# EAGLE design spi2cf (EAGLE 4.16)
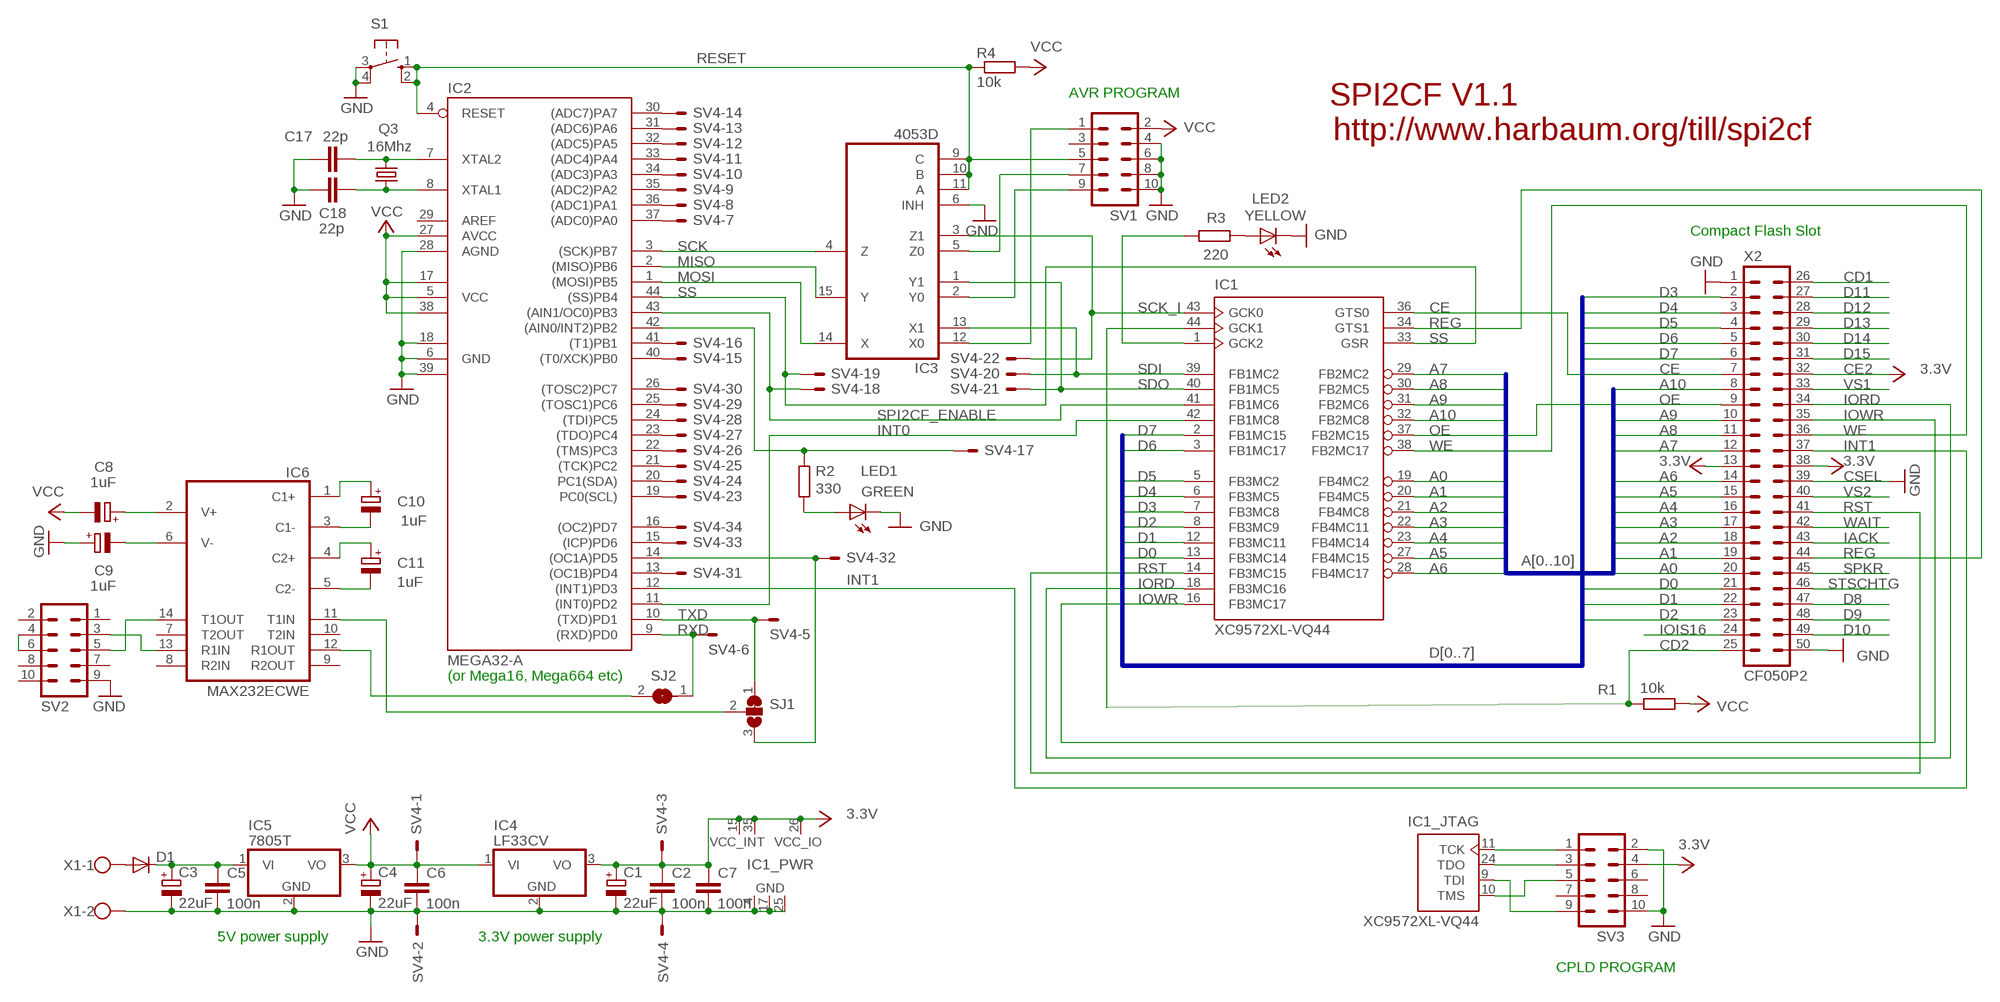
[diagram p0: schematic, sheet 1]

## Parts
C1  22uF  CPOL-EUCT6032  [CT6032]
C2  100n  C-EUC0805  [C0805]
C3  22uF  CPOL-EUCT6032  [CT6032]
C4  22uF  CPOL-EUCT6032  [CT6032]
C5  100n  C-EUC0805  [C0805]
C6  100n  C-EUC0805  [C0805]
C7  100n  C-EUC0805  [C0805]
C8  1uF  CPOL-EUCT3216  [CT3216]
C9  1uF  CPOL-EUCT3216  [CT3216]
C10  1uF  CPOL-EUCT3216  [CT3216]
C11  1uF  CPOL-EUCT3216  [CT3216]
C17  22p  C-EUC0805  [C0805]
C18  22p  C-EUC0805  [C0805]
D1  DIODE-SMC  [SMC]
IC1  XC9572XL-VQ44  [VQ44]
IC2  MEGA32-A  [TQFP44]
IC3  4053D  [SO16]
IC4  LF33CV  7805T  [TO220H]
IC5  7805T  [TO220H]
IC6  MAX232ECWE  [SO16L]
LED1  GREEN  LEDCHIPLED_0805  [CHIPLED_0805]
LED2  YELLOW  LEDCHIPLED_0805  [CHIPLED_0805]
Q3  16Mhz  CRYTALHC49S  [HC49/S]
R1  10k  R-EU_R0805  [R0805]
R2  330  R-EU_R0805  [R0805]
R3  220  R-EU_R0805  [R0805]
R4  10k  R-EU_R0805  [R0805]
S1  10-XX  [B3F-10XX]
SJ1  SJ2W  [SJ_2]
SJ2  SJ  [SJ]
SV1  ML10  [ML10]
SV2  ML10  [ML10]
SV3  ML10  [ML10]
SV4  ML34E  [ML34]
X1  W237-02P  [W237-132]
X2  CF050P2  [CF050P2]

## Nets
A0: IC1.19(FB4MC2) X2.20
A1: IC1.20(FB4MC5) X2.19
A2: IC1.21(FB4MC8) X2.18
A3: IC1.22(FB4MC11) X2.17
A4: IC1.23(FB4MC14) X2.16
A5: IC1.27(FB4MC15) X2.15
A6: IC1.28(FB4MC17) X2.14
A7: IC1.29(FB2MC2) X2.12
A8: IC1.30(FB2MC5) X2.11
A9: IC1.31(FB2MC6) X2.10
A10: IC1.32(FB2MC8) X2.8
CE: IC1.36(GTS0) X2.7
D0: IC1.13(FB3MC14) X2.21
D1: IC1.12(FB3MC11) X2.22
D2: IC1.8(FB3MC9) X2.23
D3: IC1.7(FB3MC8) X2.2
D4: IC1.6(FB3MC5) X2.3
D5: IC1.5(FB3MC2) X2.4
D6: IC1.3(FB1MC17) X2.5
D7: IC1.2(FB1MC15) X2.6
D8: X2.47
D9: X2.48
D10: X2.49
GND [power]: C1.- C2.2 C3.- C4.- C5.2 C6.2 C7.2 C9.+ C17.1 C18.1 IC1.4(GND) IC1.17(GND) IC1.25(GND) IC2.6(GND) IC2.18(GND1) IC2.28(AGND) IC2.39(GND2) IC3.6(INH) IC4.2(GND) IC5.2(GND) LED1.C LED2.C S1.3(P) S1.4(P1) SV1.4 SV1.6 SV1.8 SV1.10 SV2.9 SV3.2 SV3.10 SV4.2 SV4.4 X1.2 X2.1 X2.39 X2.50
IACK: X2.43
INT0: IC1.42(FB1MC8) IC2.11((INT0)PD2)
INT1: IC2.12((INT1)PD3) X2.37
IORD: IC1.18(FB3MC16) X2.34
IOWR: IC1.16(FB3MC17) X2.35
LED1: IC2.42((AIN0/INT2)PB2) R2.2 SV4.17
LED2: IC1.1(GCK2) R3.2
MISO: IC3.2(Y0) SV1.9
MOSI: IC3.12(X0) SV1.1
N$1: X2.24
N$2: IC1.11(TCK) SV3.1
N$3: IC1.24(TDO) SV3.3
N$4: IC1.10(TMS) SV3.5
N$5: IC2.16((OC2)PD7) SV4.34
N$6: IC1.9(TDI) SV3.9
N$7: IC1.44(GCK1) R1.2 X2.25
N$8: X2.27
N$9: IC2.2((MISO)PB6) IC3.15(Y)
N$10: IC2.3((SCK)PB7) IC3.4(Z)
N$11: D1.A X1.1
N$12: C3.+ C5.1 D1.C IC5.1(VI)
N$13: C18.2 IC2.8(XTAL1) Q3.1
N$14: C17.2 IC2.7(XTAL2) Q3.2
N$15: IC2.1((MOSI)PB5) IC3.14(X)
N$16: X2.28
N$17: X2.29
N$18: LED1.A R2.1
N$19: X2.26
N$20: IC2.37((ADC0)PA0) SV4.7
N$21: IC2.36((ADC1)PA1) SV4.8
N$22: IC2.35((ADC2)PA2) SV4.9
N$23: IC2.34((ADC3)PA3) SV4.10
N$24: IC2.33((ADC4)PA4) SV4.11
N$25: SV2.4 SV2.6
N$26: IC6.13(R1IN) SV2.3
N$27: IC6.14(T1OUT) SV2.5
N$28: C10.+ IC6.1(C1+)
N$29: C10.- IC6.3(C1-)
N$30: IC2.32((ADC5)PA5) SV4.12
N$31: C11.+ IC6.4(C2+)
N$32: IC2.31((ADC6)PA6) SV4.13
N$33: C11.- IC6.5(C2-)
N$34: IC2.30((ADC7)PA7) SV4.14
N$35: IC2.40((T0/XCK)PB0) SV4.15
N$36: IC2.41((T1)PB1) SV4.16
N$37: LED2.A R3.1
N$38: IC2.23((TDO)PC4) SV4.27
N$39: IC2.19(PC0(SCL)) SV4.23
N$40: IC2.20(PC1(SDA)) SV4.24
N$41: IC2.21((TCK)PC2) SV4.25
N$42: IC2.22((TMS)PC3) SV4.26
N$43: IC2.24((TDI)PC5) SV4.28
N$44: IC2.25((TOSC1)PC6) SV4.29
N$45: IC2.26((TOSC2)PC7) SV4.30
N$46: IC2.15((ICP)PD6) SV4.33
N$47: IC2.14((OC1A)PD5) SJ1.3 SV4.32
N$48: IC2.13((OC1B)PD4) SV4.31
N$49: X2.30
N$50: X2.31
N$51: X2.33
OE: IC1.37(FB2MC15) X2.9
REG: IC1.34(GTS1) X2.44
RESET: IC2.4(RESET) IC3.9(C) IC3.10(B) IC3.11(A) R4.1 S1.1(S) S1.2(S1) SV1.5
RST: IC1.14(FB3MC15) X2.41
RXD: IC2.9((RXD)PD0) SJ2.1 SV4.6
RXD_MAX: IC6.12(R1OUT) SJ2.2
SCK: IC3.5(Z0) SV1.7
SCK_I: IC1.43(GCK0) IC3.3(Z1) SV4.22
SDI: IC1.39(FB1MC2) IC3.13(X1) SV4.20
SDO: IC1.40(FB1MC5) IC3.1(Y1) SV4.21
SPI2CF_ENABLE: IC1.41(FB1MC6) IC2.43((AIN1/OC0)PB3) SV4.18
SPKR: X2.45
SS: IC1.33(GSR) IC2.44((SS)PB4) SV4.19
STSCHTG: X2.46
TXD: IC2.10((TXD)PD1) SJ1.1 SV4.5
TXD_MAX: IC6.11(T1IN) SJ1.2
V33: C1.+ C2.1 C7.1 IC1.15(VCC_INT) IC1.26(VCC_IO) IC1.35(VCC_INT) IC4.3(VO) SV3.4 SV4.3 X2.13 X2.32 X2.38 ; supply symbol labelled 3.3V
V+: C8.+ IC6.2(V+)
V-: C9.- IC6.6(V-)
VCC [power]: C4.+ C6.1 C8.- IC2.5(VCC) IC2.17(VCC1) IC2.27(AVCC) IC2.38(VCC2) IC4.1(VI) IC5.3(VO) R1.1 R4.2 SV1.2 SV4.1
VS2: X2.40
WAIT: X2.42
WE: IC1.38(FB2MC17) X2.36
Unconnected: IC6.7(T2OUT) IC6.8(R2IN) IC6.9(R2OUT) IC6.10(T2IN) SV1.3 SV2.1 SV2.2 SV2.7 SV2.8 SV2.10 SV3.6 SV3.7 SV3.8

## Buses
A[0..10]
D[0..7]

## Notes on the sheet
- AVR PROGRAM
- SPI2CF V1.1
- http://www.harbaum.org/till/spi2cf
- Compact Flash Slot
- CD1
- D11
- D12
- D13
- D14
- D15
- CE2
- VS1
- CSEL
- IOIS16
- CD2
- (or Mega16, Mega664 etc)
- 5V power supply | 3.3V power supply
- CPLD PROGRAM

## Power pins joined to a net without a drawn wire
AREF: IC2.29(AREF)
GND: IC3.8(GND) IC6.15(GND)
VCC: IC3.16(VCC) IC6.16(VCC)
VEE: IC3.7(VEE)

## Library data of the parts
C1 C3 C4 C8-C11 = rcl:CPOL-EU: POLARIZED CAPACITOR, European symbol
C2 C5-C7 C17 C18 = rcl:C-EU: CAPACITOR, European symbol
D1 = diode:DIODE-: DIODE
IC1 = XC9500XLneu:XC9572XL-VQ44
IC2 = avr:MEGA32: MICROCONTROLLER 32 Kbytes FLASH 2 Kbytes SRAM 1 Kbytes EEPROM USART 8-channel 10 bit ADC
IC3 = 40xx:4053: Triple 2-channel ANALOG MULTIPLEXER
IC4 IC5 = linear:78*: Positive VOLTAGE REGULATOR Source: http://cache.national.com/ds/LM/LM78L05.pdf http://www.fairchildsemi.com/ds/LM/LM7805.pdf
IC6 = maxim:MAX232ECWE: RS232 TRANSEIVER
LED1 LED2 = led:LED: LED
Q3 = crystal:CRYTAL: CRYSTAL
R1-R4 = rcl:R-EU_: RESISTOR, European symbol
S1 = switch-omron:10-XX: OMRON SWITCH
SJ1 = jumper:SJ2W: SMD solder JUMPER
SJ2 = jumper:SJ: SMD solder JUMPER
SV1-SV3 = con-ml:ML10: HARTING
SV4 = con-ml:ML34E: HARTING
X1 = con-wago-508:W237-02P: WAGO SREW CLAMP
X2 = con-yamaichi-cf:CF050P2: Compact Flash Card Reader, Type I and II CF 050 P2 - * 03 - * 0 - DS

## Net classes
1 power: width 0.635 mm, drill 0.254 mm

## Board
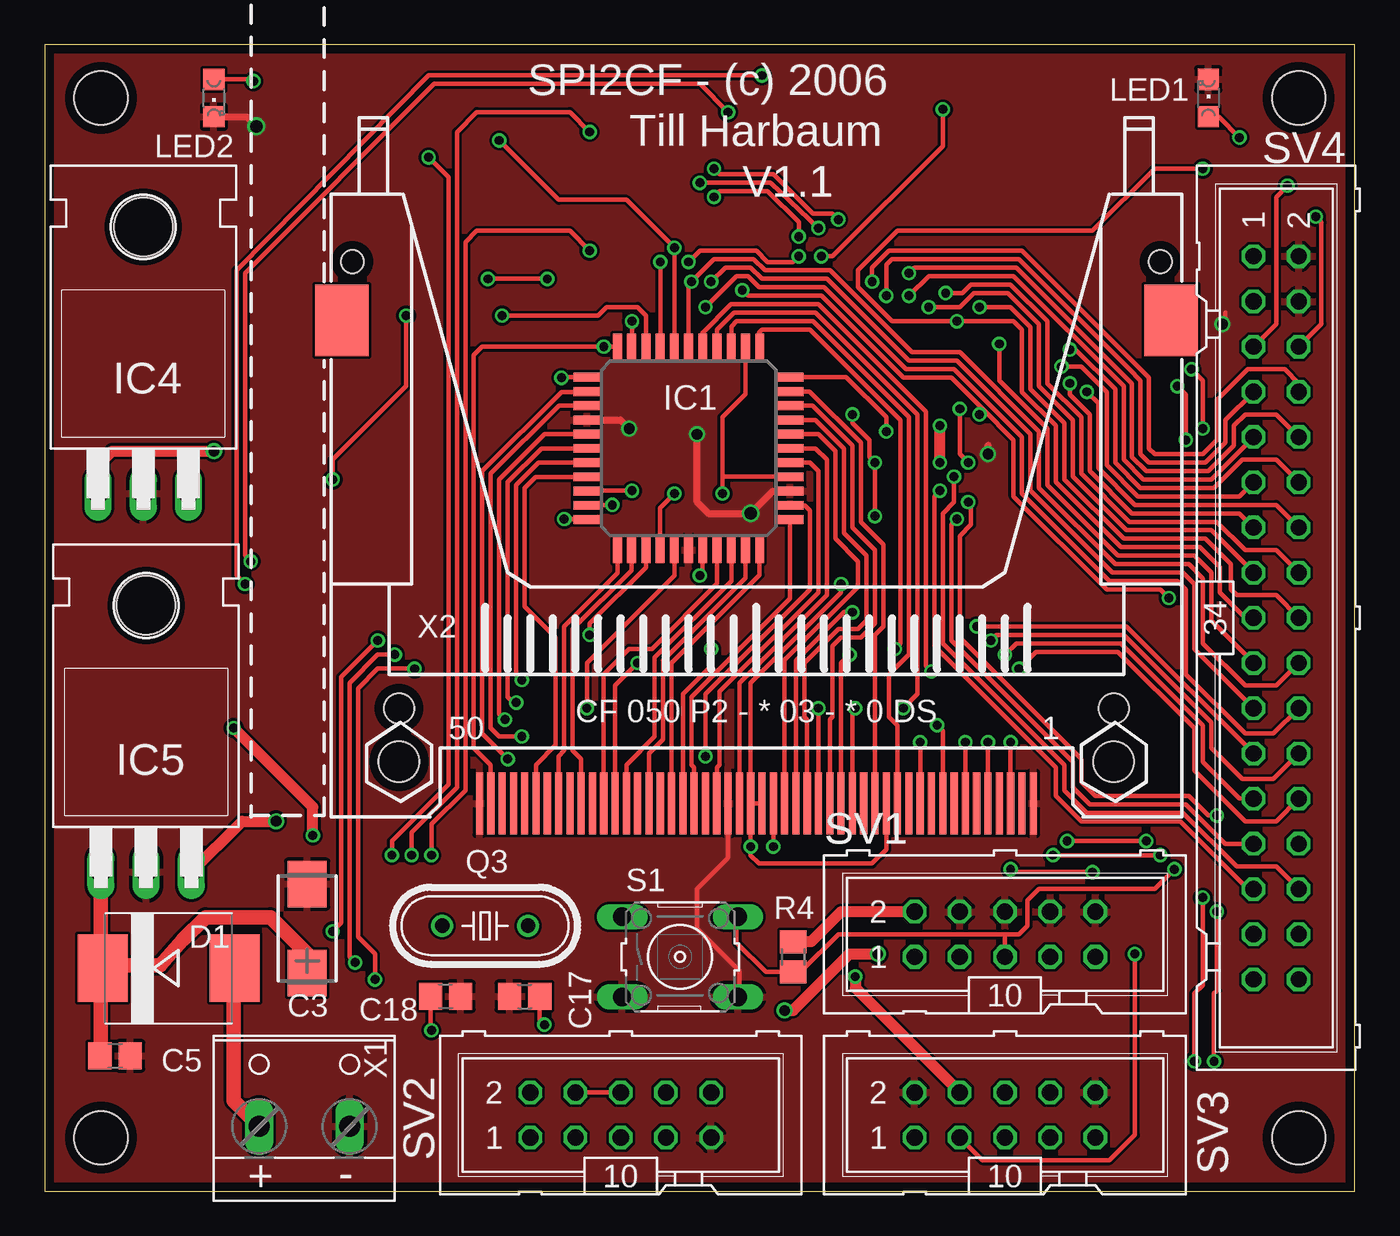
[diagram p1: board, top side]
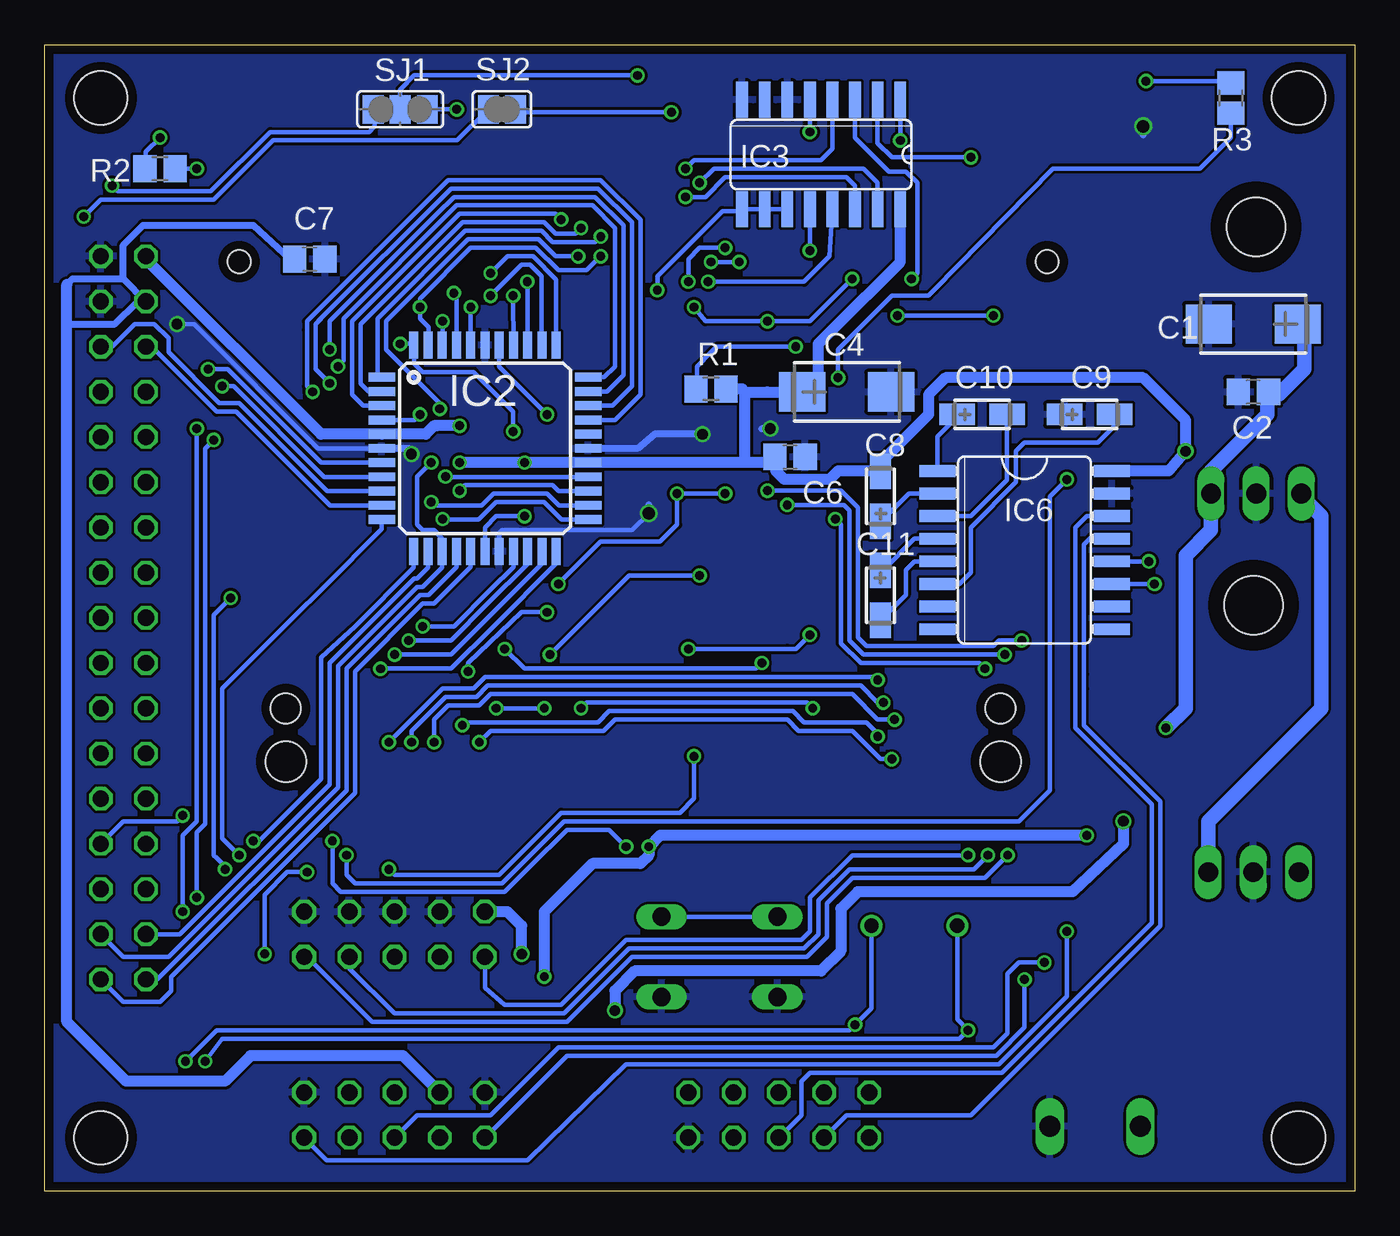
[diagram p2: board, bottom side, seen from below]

Size 73.64 x 64.44 mm. Coordinates in mm from the lower left corner, seen from the top.
Outline: 0,0 73.64,0 73.64,64.44 0,64.44 0,0
Copper layers (1*16): Top 0.035mm / dielectric 1.5mm / Bottom 0.035mm
Design rules "PCB-POOL": minimum track width 6mil, minimum drill 12mil, track to track 6mil, track to pad 6mil, pad to pad 6mil, via to via 6mil, smd to smd 6mil, copper to edge 20mil, drill to drill 8mil, minimum pad ring 8mil, minimum via ring 6mil, stop-mask expansion 3mil, vias tented up to drill 0mil, thermal gap 8mil
Holes 3 mm at 3.17,61.43 3.17,3.01 70.48,61.43 70.48,3.01

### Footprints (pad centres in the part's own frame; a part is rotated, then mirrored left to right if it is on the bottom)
CT6032 = smd 2.6 x 2.2: + 2.5,0; - -2.5,0
C0805 = smd 1.3 x 1.5: 1 -0.85,0; 2 0.85,0
CT3216 = smd 2 x 1.2: + 1.4,0; - -1.4,0
SMC = smd 2.8 x 3.8: A 3.7,0; C -3.7,0
VQ44 = smd 1.5 x 0.5: 1 -5.7,4; 2 -5.7,3.2; 3 -5.7,2.4; 4 -5.7,1.6; 5 -5.7,0.8; 6 -5.7,0; 7 -5.7,-0.8; 8 -5.7,-1.6; 9 -5.7,-2.4; 10 -5.7,-3.2; 11 -5.7,-4; 23 5.7,-4; 24 5.7,-3.2; 25 5.7,-2.4; 26 5.7,-1.6; 27 5.7,-0.8; 28 5.7,0; 29 5.7,0.8; 30 5.7,1.6; 31 5.7,2.4; 32 5.7,3.2; 33 5.7,4 | smd 0.5 x 1.5: 12 -4,-5.7; 13 -3.2,-5.7; 14 -2.4,-5.7; 15 -1.6,-5.7; 16 -0.8,-5.7; 17 0,-5.7; 18 0.8,-5.7; 19 1.6,-5.7; 20 2.4,-5.7; 21 3.2,-5.7; 22 4,-5.7; 34 4,5.7; 35 3.2,5.7; 36 2.4,5.7; 37 1.6,5.7; 38 0.8,5.7; 39 0,5.7; 40 -0.8,5.7; 41 -1.6,5.7; 42 -2.4,5.7; 43 -3.2,5.7; 44 -4,5.7
TQFP44 = smd 1.5 x 0.5: 1 -5.8,4; 2 -5.8,3.2; 3 -5.8,2.4; 4 -5.8,1.6; 5 -5.8,0.8; 6 -5.8,0; 7 -5.8,-0.8; 8 -5.8,-1.6; 9 -5.8,-2.4; 10 -5.8,-3.2; 11 -5.8,-4; 23 5.8,-4; 24 5.8,-3.2; 25 5.8,-2.4; 26 5.8,-1.6; 27 5.8,-0.8; 28 5.8,0; 29 5.8,0.8; 30 5.8,1.6; 31 5.8,2.4; 32 5.8,3.2; 33 5.8,4 | smd 0.5 x 1.5: 12 -4,-5.8; 13 -3.2,-5.8; 14 -2.4,-5.8; 15 -1.6,-5.8; 16 -0.8,-5.8; 17 0,-5.8; 18 0.8,-5.8; 19 1.6,-5.8; 20 2.4,-5.8; 21 3.2,-5.8; 22 4,-5.8; 34 4,5.8; 35 3.2,5.8; 36 2.4,5.8; 37 1.6,5.8; 38 0.8,5.8; 39 0,5.8; 40 -0.8,5.8; 41 -1.6,5.8; 42 -2.4,5.8; 43 -3.2,5.8; 44 -4,5.8
SO16 = smd 0.66 x 2.032: 1 -4.445,-3.073; 2 -3.175,-3.073; 3 -1.905,-3.073; 4 -0.635,-3.073; 5 0.635,-3.073; 6 1.905,-3.073; 7 3.175,-3.073; 8 4.445,-3.073; 9 4.445,3.073; 10 3.175,3.073; 11 1.905,3.073; 12 0.635,3.073; 13 -0.635,3.073; 14 -1.905,3.073; 15 -3.175,3.073; 16 -4.445,3.073
TO220H = drill 1.118 long: 1 -2.54,-10.16; 2 0,-10.16; 3 2.54,-10.16 | hole 3.302: 0,4.826
SO16L = smd 0.66 x 2.032: 1 -4.445,-4.902; 2 -3.175,-4.902; 3 -1.905,-4.902; 4 -0.635,-4.902; 5 0.635,-4.902; 6 1.905,-4.902; 7 3.175,-4.902; 8 4.445,-4.902; 9 4.445,4.902; 10 3.175,4.902; 11 1.905,4.902; 12 0.635,4.902; 13 -0.635,4.902; 14 -1.905,4.902; 15 -3.175,4.902; 16 -4.445,4.902
CHIPLED_0805 = smd 1.2 x 1.2: A 0,-1.05; C 0,1.05
HC49/S = drill 0.813 round: 1 -2.413,0; 2 2.413,0
R0805 = smd 1.3 x 1.5: 1 -0.85,0; 2 0.85,0
B3F-10XX = drill 1.016 long: 1 -3.251,2.261; 2 3.251,2.261; 3 -3.251,-2.261; 4 3.251,-2.261
SJ_2 = smd 1.168 x 1.6: 1 -1.524,0; 2 0,0; 3 1.524,0
SJ = smd 1.168 x 1.6: 1 -0.762,0; 2 0.762,0
ML10 = drill 0.914 octagon: 1 -5.08,-1.27; 2 -5.08,1.27; 3 -2.54,-1.27; 4 -2.54,1.27; 5 0,-1.27; 6 0,1.27; 7 2.54,-1.27; 8 2.54,1.27; 9 5.08,-1.27; 10 5.08,1.27
ML34 = drill 0.914 octagon: 1 -20.32,-1.27; 2 -20.32,1.27; 3 -17.78,-1.27; 4 -17.78,1.27; 5 -15.24,-1.27; 6 -15.24,1.27; 7 -12.7,-1.27; 8 -12.7,1.27; 9 -10.16,-1.27; 10 -10.16,1.27; 11 -7.62,-1.27; 12 -7.62,1.27; 13 -5.08,-1.27; 14 -5.08,1.27; 15 -2.54,-1.27; 16 -2.54,1.27; 17 0,-1.27; 18 0,1.27; 19 2.54,-1.27; 20 2.54,1.27; 21 5.08,-1.27; 22 5.08,1.27; 23 7.62,-1.27; 24 7.62,1.27; 25 10.16,-1.27; 26 10.16,1.27; 27 12.7,-1.27; 28 12.7,1.27; 29 15.24,-1.27; 30 15.24,1.27; 31 17.78,-1.27; 32 17.78,1.27; 33 20.32,-1.27; 34 20.32,1.27
W237-132 = drill 1.194 long: 1 -2.54,-0.635; 2 2.54,-0.635
CF050P2 = smd 0.4 x 3.5: 1 15.557,-5.35; 2 14.287,-5.35; 3 13.018,-5.35; 4 11.748,-5.35; 5 10.477,-5.35; 6 9.207,-5.35; 7 7.938,-5.35; 8 6.668,-5.35; 9 5.397,-5.35; 10 4.128,-5.35; 11 2.857,-5.35; 12 1.587,-5.35; 13 0.318,-5.35; 14 -0.953,-5.35; 15 -2.223,-5.35; 16 -3.493,-5.35; 17 -4.763,-5.35; 18 -6.032,-5.35; 19 -7.303,-5.35; 20 -8.572,-5.35; 21 -9.842,-5.35; 22 -11.113,-5.35; 23 -12.383,-5.35; 24 -13.652,-5.35; 25 -14.922,-5.35; 26 14.922,-5.35; 27 13.652,-5.35; 28 12.383,-5.35; 29 11.113,-5.35; 30 9.842,-5.35; 31 8.572,-5.35; 32 7.303,-5.35; 33 6.032,-5.35; 34 4.763,-5.35; 35 3.493,-5.35; 36 2.223,-5.35; 37 0.953,-5.35; 38 -0.318,-5.35; 39 -1.587,-5.35; 40 -2.857,-5.35; 41 -4.128,-5.35; 42 -5.397,-5.35; 43 -6.668,-5.35; 44 -7.938,-5.35; 45 -9.207,-5.35; 46 -10.477,-5.35; 47 -11.748,-5.35; 48 -13.018,-5.35; 49 -14.287,-5.35; 50 -15.557,-5.35 | smd 3 x 4: P$1 23.3,21.8; P$3 -23.3,21.8 | hole 1.7: -20.08,0; 20.08,0 | hole 2.3: -20.08,-3; 20.08,-3 | hole 1.3: 22.7,25.1; -22.7,25.1

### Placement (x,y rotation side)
C1  5.71,48.73 0 bottom
C2  5.71,44.92 180 bottom
C3  14.76,14.76 270 top
C4  28.57,44.92 180 bottom
C5  3.96,7.61 0 top
C6  31.74,41.27 0 bottom
C7  58.73,52.38 0 bottom
C8  26.67,39.05 270 bottom
C9  14.92,43.65 180 bottom
C10  20.95,43.65 180 bottom
C11  26.66,33.49 90 bottom
C17  26.98,10.95 0 top
C18  22.54,10.95 180 top
D1  6.98,12.54 0 top
IC1  36.19,41.74 0 top
IC2  48.89,41.74 0 bottom
IC3  30,58.25 180 bottom
IC4  5.55,49.37 0 top
IC5  5.71,28.09 0 top
IC6  18.57,36.03 270 bottom
LED1  65.4,61.43 0 top
LED2  9.52,61.43 180 top
Q3  24.76,14.92 0 top
R1  36.19,45.08 180 bottom
R2  67.15,57.46 0 bottom
R3  6.98,61.43 270 bottom
R4  42.06,13.17 90 top
S1  35.71,13.17 0 top
SJ1  53.65,60.8 0 bottom
SJ2  47.94,60.8 0 bottom
SV1  53.97,14.44 0 top
SV2  32.38,4.28 0 top
SV3  53.97,4.28 0 top
SV4  69.21,32.22 270 top
X1  14.6,4.28 0 top
X2  40,27.14 0 top

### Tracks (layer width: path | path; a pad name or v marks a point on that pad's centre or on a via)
A0
  Top 0.254: IC1.19 37.79,34.14 34.13,30.47 32.86,30.47 31.43,29.04 X2.20
A1
  Top 0.254: IC1.20 38.59,34.3 34.29,30 34.29,25.55 32.7,23.96 X2.19
A2
  Top 0.254: IC1.21 39.39,34.47 34.76,29.84 34.76,25.39 33.97,24.6 X2.18
A3
  Top 0.254: IC1.22 40.19,34.63 35.24,29.68 X2.17
A4
  Top 0.254: X2.16 36.51,23.81 36.35,23.96 36.35,27.77 41.89,33.32 IC1.23
A5
  Top 0.254: X2.15 37.78,23.81 37.94,23.96 37.94,28.09 43.49,33.65 43.49,40.48 43.02,40.95 IC1.27
A6
  Top 0.254: X2.14 39.05,28.57 43.97,33.49 43.97,41.11 43.33,41.74 IC1.28
A7
  Top 0.254: X2.12 41.59,28.09 41.59,29.84 45.72,33.97 45.72,35.39 44.45,36.66 44.45,41.59 43.49,42.55 IC1.29
A8
  Top 0.254: IC1.30 43.32,43.34 44.92,41.74 44.92,36.98 46.19,35.71 46.19,32.06 45.72,31.58 44.6,31.58 42.7,29.68 42.7,26.66 42.86,26.5 X2.11
A9
  Top 0.254: X2.10 44.13,26.5 44.29,26.66 44.29,30.63 44.76,31.11 45.87,31.11 46.67,31.9 46.67,36.03 45.4,37.3 45.4,41.9 43.16,44.14 IC1.31
A10
  Top 0.254: IC1.32 42.99,44.95 45.87,42.06 45.87,37.62 47.14,36.35 47.14,31.74 46.67,31.27 X2.8
CE
  Top 0.254: IC1.36 38.59,48.59 38.89,48.89 43.18,48.89 48.57,43.49 48.57,34.6 48.57,30.16 48.1,29.68 47.46,29.04 47.46,26.66 47.94,26.19 X2.7
D0
  Top 0.254: IC1.13 32.99,34.89 29.68,31.58 29.68,24.76 30.16,24.28 X2.21
D1
  Top 0.254: IC1.12 32.19,34.73 29.2,31.74 29.2,24.76 28.89,24.44 X2.22
D2
  Top 0.254: X2.23 27.62,23.96 28.73,25.08 28.73,31.11 26.98,32.85 26.98,39.52 27.61,40.14 IC1.8
D3  (via drill 0.5)
  Top 0.254: v54.29,25.23 X2.2 | v26.82,28.73 26.51,29.04 26.51,39.68 27.77,40.95 IC1.7
  Bottom 0.254: v26.82,28.73 26.82,28.89 48.89,28.89 49.53,28.25 51.27,28.25 v54.29,25.23
D4  (via drill 0.5)
  Top 0.254: v53.02,25.23 X2.3 | v26.51,27.46 26.35,27.46 26.03,27.77 26.03,39.84 27.93,41.74 IC1.6
  Bottom 0.254: v26.51,27.46 26.82,27.46 27.78,28.41 48.73,28.41 49.37,27.77 51.11,27.77 53.02,25.87 v53.02,25.23
D5  (via drill 0.5)
  Top 0.254: v51.75,25.23 X2.4 | v25.87,26.5 25.55,26.82 25.55,40 28.1,42.55 IC1.5
  Bottom 0.254: v51.75,25.23 51.75,26.5 50.95,27.3 49.21,27.3 48.57,27.93 28.25,27.93 26.82,26.5 v25.87,26.5
D6  (via drill 0.5)
  Top 0.254: 50.48,21.74 X2.5 50.48,25.87 v50.16,26.19 | v26.82,25.55 25.55,25.55 25.08,26.03 25.08,40.32 28.91,44.14 IC1.3
  Bottom 0.254: v50.16,26.19 50,26.35 42.54,26.35 41.91,26.98 31.59,26.98 30.95,26.35 27.46,26.35 26.82,25.71 | v26.82,25.55 26.82,25.71 | 26.82,25.71
D7  (via drill 0.5)
  Top 0.254: v49.21,25.23 49.21,23.81 | 49.21,23.81 | 49.21,23.81 X2.6 | v26.03,24.28 24.6,25.71 24.6,40.48 29.05,44.92 30.47,44.92 30.49,44.94 IC1.2
  Bottom 0.254: v26.03,24.28 26.66,24.28 28.25,25.87 31.27,25.87 31.9,26.5 41.59,26.5 42.22,25.87 48.57,25.87 v49.21,25.23
GND  (via drill 0.6, 0.7)
  Top 0.254: X2.39 38.41,18.73 36.67,16.98 36.67,14.76 39.05,12.38 39.05,10.95 38.97,10.87 | 38.97,10.87 38.89,10.79 | S1.4 38.97,10.87 | v66.19,48.73 66.35,48.89 66.35,49.37
  Top 0.406: LED2.C 11.36,60.38 v11.9,59.84 | IC1.25 40.93,39.34 v39.68,38.09 37.3,38.09 36.67,38.73 v36.67,42.54 | v53.02,41.43 53.02,41.9 | IC1.4 32.37,43.34 v32.86,42.86
  Bottom 0.254: IC2.18 48.09,36.99 47.94,37.14 40.64,37.14 v39.68,38.09 | v53.02,41.43 53.34,41.74 58.26,41.74 65.24,48.73 v66.19,48.73
  Bottom 0.406: v11.9,59.84 11.9,59.37 | v39.68,38.09 39.68,38.57 | IC2.28 40.32,41.74 39.37,42.54 v36.67,42.54 | IC2.6 53.18,41.74 v53.02,41.43 | v32.86,42.86 33.33,42.86
  pour Bottom: -0.01,-0.01 -0.01,64.45 73.66,64.45 73.66,-0.01
  pour Top: -0.01,-0.01 -0.01,64.45 73.66,64.45 73.66,64.45 73.66,-0.01
INT0  (via drill 0.5)
  Top 0.254: v56.67,18.88 v62.7,18.88 | v16.19,40 16.19,41.11 20.31,45.24 v20.31,49.21 | v25.71,49.21 31.11,49.21 31.59,49.68 33.33,49.68 33.81,49.21 33.81,47.46 IC1.42
  Bottom 0.254: IC2.11 54.69,37.21 57.94,33.97 59.69,32.22 63.65,28.25 63.65,19.84 v62.7,18.88 | v62.7,18.88 | v56.67,18.88 56.67,17.77 56.19,17.3 47.94,17.3 44.45,20.79 33.65,20.79 | 33.65,20.79 18.89,20.79 17.14,22.54 17.14,39.05 v16.19,40 | 33.65,20.79 | v20.31,49.21 v25.71,49.21
INT1  (via drill 0.5)
  Top 0.254: v61.91,19.68 61.59,19.68 v57.46,19.68 | 40.95,21.9 X2.37 v40.95,19.36
  Bottom 0.254: IC2.12 52.89,35.05 56.19,31.74 58.1,30 58.1,23.17 61.59,19.68 v61.91,19.68 | v57.46,19.68 57.46,19.84 57.46,17.3 56.99,16.82 47.78,16.82 46.35,18.25 44.29,20.31 41.91,20.31 v40.95,19.36
IORD  (via drill 0.5)
  Top 0.254: X2.34 44.76,29.68 v45.24,30.16 | IC1.18 36.98,34.76 v36.83,34.6
  Bottom 0.254: v45.24,30.16 40.79,34.6 v36.83,34.6
IOWR  (via drill 0.5)
  Top 0.254: v43.49,27.14 X2.35 | v30.47,27.14 30.47,29.68 35.39,34.59 IC1.16
  Bottom 0.254: v30.47,27.14 30.79,27.46 43.18,27.46 v43.49,27.14
LED1  (via drill 0.5)
  Top 0.254: SV4.17 67.46,32.22 66.03,33.65 66.03,35.08 64.92,36.19 60.48,36.19 56.83,39.84 56.83,43.02 54.92,44.92 54.92,48.41 | 54.92,48.41 54.45,48.89 v51.27,48.89 47.62,48.89 45.72,50.79 45.72,51.75 47.94,53.97 58.89,53.97 62.38,57.46 v65.08,57.46 | 54.92,48.41 54.92,48.25
  Bottom 0.254: IC2.42 51.19,47.55 51.27,47.62 v51.27,48.89 | R2.2 v65.08,57.46
LED2  (via drill 0.5)
  Top 0.254: IC1.1 29.05,45.74 v29.05,45.71
  Bottom 0.254: 26.03,50.32 23.97,50.32 23.65,50.63 16.98,57.46 8.73,57.46 6.98,59.21 6.98,60.48 | 26.03,50.32 | 26.03,50.32 29.05,47.3 v29.05,45.71 | 6.98,60.48 | R3.2 6.98,60.48
MISO  (via drill 0.5)
  Top 0.254: v19.52,18.88 19.52,19.68 22.7,22.85 22.7,56.98 v21.58,58.1
  Bottom 0.254: SV1.9 58.89,13.17 55.24,9.52 44.29,9.52 40.64,13.17 39.84,13.17 30.79,13.17 29.68,14.28 29.68,16.19 28.25,17.61 20.79,17.61 v19.52,18.88 | v21.58,58.1 26.03,58.1 26.82,58.89 IC3.2
MOSI  (via drill 0.5)
  Top 0.254: v21.74,18.88 | v21.74,18.88 21.74,20.63 23.65,22.54 23.65,53.33 24.28,53.97 29.52,53.97 v30.63,52.86
  Bottom 0.254: SV1.1 48.89,11.42 47.78,10.47 44.6,10.47 40.95,14.12 31.11,14.12 30.63,14.6 30.63,16.5 28.25,18.88 v21.74,18.88 | v21.74,18.88 | 30.63,55.24 IC3.12 v30.63,52.86
N$2  (via drill 0.5)
  Top 0.254: IC1.11 30.52,37.78 v29.2,37.78 | v18.57,11.9 18.57,13.33 17.62,14.28 17.62,21.74 17.62,27.77 17.62,28.25 18.73,29.36 v20.79,29.36
  Bottom 0.254: SV3.1 44.29,7.61 20.16,7.61 18.57,9.2 v18.57,11.9 | v20.79,29.36 21.11,29.68 27.78,29.68 28.89,30.79 28.89,37.46 v29.2,37.78
N$3  (via drill 0.5)
  Top 0.254: IC1.24 42.72,38.55 43.02,38.25 43.02,33.81 37.14,27.93 v37.14,24.44 | v58.89,17.93 54.45,17.93 v54.29,18.09 | v54.29,18.09 | v61.27,13.33 61.27,3.17 60.48,2.38 59.84,1.74 52.7,1.74 SV3.3
  Bottom 0.254: v37.14,24.44 37.14,22.06 37.94,21.27 44.6,21.27 48.1,17.77 53.97,17.77 | 53.97,17.77 | 53.97,17.77 | 53.97,17.77 | 53.97,17.77 54.13,17.93 v54.29,18.09 | v61.27,13.33 61.27,16.66 60,17.93 v58.89,17.93
N$4  (via drill 0.5)
  Top 0.254: IC1.10 30.52,38.57 v31.9,38.57 | v19.68,30.16 18.73,30.16 17.14,28.57 17.14,13.17 v17.46,12.85
  Bottom 0.254: SV3.5 52.7,4.28 48.57,4.28 44.76,8.09 20.31,8.09 19.52,8.88 19.52,12.22 18.89,12.85 v17.46,12.85 | v19.68,30.16 | v19.68,30.16 27.62,30.16 28.41,30.95 28.41,38.25 28.73,38.57 v31.9,38.57
N$5
  Bottom 0.254: IC2.16 49.69,35.07 51.75,33.01 52.38,33.01 56.19,29.2 56.19,22.38 66.51,12.06 66.51,11.27 67.15,10.63 69.21,10.63 SV4.34
N$6  (via drill 0.5)
  Top 0.254: IC1.9 30.51,39.36 v33.02,39.36 | v18.73,30.95 16.66,28.89 16.66,28.73 16.66,27.3 16.66,15.08 v16.19,14.6
  Bottom 0.254: v18.73,30.95 20,30.95 20.31,30.63 27.46,30.63 27.93,31.11 27.93,38.41 28.89,39.36 v33.02,39.36 | SV3.9 57.78,1.74 46.51,1.74 40.95,7.14 20,7.14 16.19,10.95 v16.19,14.6
N$7  (via drill 0.5)
  Top 0.254: X2.25 25.08,23.96 24.12,24.92 24.12,46.98 24.6,47.46 v31.43,47.46 32.06,47.46 32.19,47.65 IC1.44
  Bottom 0.254: R1.2 36.98,45.08 36.98,46.35 36.19,47.14 | 36.19,47.14 | 36.19,47.14 35.87,47.46 v31.43,47.46
N$9  (via drill 0.5)
  Top 0.254: v43.49,54.13 40.79,56.67 v36.83,56.67
  Bottom 0.254: 55.42,44.95 IC2.2 | 55.42,44.95 55.88,45.4 55.88,46.19 | 55.42,44.95 | 55.88,46.19 55.88,48.73 50.16,54.45 46.51,54.45 45.56,54.45 44.92,53.81 43.81,53.81 v43.49,54.13 | 55.88,46.19 | v36.83,56.67 | v36.83,56.67 36.03,57.46 27.62,57.46 26.82,56.67 IC3.15 26.82,55.08
N$10  (via drill 0.5)
  Top 0.254: v37.62,57.46 37.94,57.14 40.95,57.14 43.18,54.92 44.29,54.92 v44.6,54.6
  Bottom 0.254: IC2.3 55.73,44.14 56.35,44.76 56.35,48.89 50.32,54.92 44.92,54.92 v44.6,54.6 | v37.62,57.46 37.14,57.94 30,57.94 29.36,58.57 IC3.4 29.36,61.43
N$11
  Top 0.813: 10.63,12.58 10.63,12.69 | 10.63,12.58 D1.A | X1.1 10.63,5.07 10.63,12.58
N$12
  Top 0.813: D1.C 3.17,12.54 3.17,7.67 C5.1 | D1.C | IC5.1 | D1.C 3.17,12.65 3.17,12.69 | 3.17,12.69 IC5.1 | C3.+ 14.76,13.33 12.7,15.39 9.04,15.39 7.77,14.12 | 7.77,14.12 | 7.77,14.12 6.5,12.69 3.17,12.69 | 3.17,12.69 3.28,12.58 D1.C
N$13  (via drill 0.5)
  Top 0.254: v63.65,45.24 63.81,45.08 64.13,44.76 v64.13,42.22 | v64.61,7.3 64.61,11.11 65.08,11.58 65.08,14.6 | 65.08,14.6 65.08,14.92 | 65.08,14.6 v65.08,16.5 | C18.2 21.69,9.1 v21.74,9.04
  Bottom 0.254: IC2.8 57.93,40.14 63.02,45.24 v63.65,45.24 | v64.13,42.22 64.61,41.74 64.61,20.63 65.08,20.15 v65.08,16.5 | 29.68,8.57 29.49,8.57 | 29.68,8.57 63.65,8.57 v64.61,7.3 | 29.68,8.57 22.22,8.57 v21.74,9.04 22.35,9.65 Q3.1
N$14  (via drill 0.5)
  Top 0.254: v64.45,46.19 65.08,45.55 v65.08,42.86 65.08,43.17 | 27.78,10.95 C17.2 27.83,9.62 v28.09,9.36 | v65.72,7.3 65.72,11.11 65.88,11.27 v65.88,15.71
  Bottom 0.254: IC2.7 58.09,40.95 63.34,46.19 | 63.65,46.19 63.34,46.19 | 63.34,46.19 63.65,46.19 | v64.45,46.19 63.65,46.19 | v65.08,42.86 65.08,20.79 65.88,20 v65.88,15.71 | v65.72,7.3 63.97,9.04 28.41,9.04 v28.09,9.36 27.17,10.28 Q3.2
N$15  (via drill 0.5)
  Top 0.254: v37.62,55.87 37.94,56.19 40.64,56.19 42.38,54.45 v42.38,53.65 | v42.38,53.65
  Bottom 0.254: IC2.1 54.95,45.74 54.92,45.71 54.92,49.05 54.76,49.21 50,53.97 45.72,53.97 45.08,53.33 42.7,53.33 v42.38,53.65 | v37.62,55.87 36.51,55.87 35.4,56.98 28.57,56.98 28.09,56.51 IC3.14
N$18  (via drill 0.5)
  Top 0.254: LED1.A 65.97,60.38 v67.15,59.21
  Bottom 0.254: v67.15,59.21 67.94,58.41 67.94,57.3 68,57.36 R2.1
N$20  (via drill 0.5)
  Top 0.254: v47.3,50.32 47.3,52.06 47.62,52.38 54.76,52.38 60.96,46.19 61.59,45.55 61.59,41.43 62.07,40.95 65.24,40.95 66.35,42.06 66.35,43.33 SV4.7
  Bottom 0.254: IC2.37 47.3,50.23 v47.3,50.32
N$21  (via drill 0.5)
  Top 0.254: v46.51,51.11 46.51,51.91 47.46,52.86 54.92,52.86 57.3,50.48 62.07,45.71 62.07,41.74 62.38,41.43 65.08,41.43 65.88,42.22 65.88,44.44 67.62,46.19 69.69,46.19 70.48,45.4 SV4.8
  Bottom 0.254: IC2.36 46.51,47.55 v46.51,51.11
N$22  (via drill 0.5)
  Top 0.254: v48.57,50.32 49.68,51.43 54.45,51.43 60.64,45.24 | 60.64,45.24 | 60.64,45.24 60.64,41.11 61.75,40 65.56,40 SV4.9 | SV4.9
  Bottom 0.254: IC2.35 45.72,47.57 45.72,51.43 46.35,52.06 46.83,52.06 v48.57,50.32
N$23  (via drill 0.5)
  Top 0.254: v48.57,51.59 48.89,51.91 49.53,51.91 54.61,51.91 61.11,45.4 61.11,41.27 61.91,40.48 65.4,40.48 66.83,41.9 66.83,43.02 67.46,43.65 | 67.46,43.65 | 67.46,43.65 69.21,43.65 SV4.10
  Bottom 0.254: IC2.34 44.89,51.24 46.19,52.54 47.62,52.54 v48.57,51.59
N$24  (via drill 0.5)
  Top 0.254: SV4.11 67.15,39.05 61.43,39.05 59.69,40.79 59.69,44.92 58.26,46.35 v57.15,46.35
  Bottom 0.254: IC2.33 42.19,45.74 41.59,46.35 41.59,54.13 42.86,55.4 45.08,55.4 45.4,55.4 50.48,55.4 56.83,49.05 56.83,46.67 v57.15,46.35
N$25
  Top 0.254: SV2.4 SV2.6
N$26
  Bottom 0.254: SV2.3 28.57,4.28 21.58,4.28 10.95,14.92 10.95,21.9 15.24,26.19 15.24,28.25 15.24,29.04 | 15.24,29.04 | 15.24,29.04 15.24,36.35 14.76,36.82 13.51,36.82 | 13.51,36.82 13.33,36.82 | 13.51,36.82 IC6.13
N$27
  Bottom 0.254: SV2.5 31.11,4.28 31.11,6.18 30.63,6.66 19.84,6.66 11.43,15.08 11.43,21.74 15.71,26.03 15.71,37.3 15.08,37.94 IC6.14 13.65,37.94
N$28
  Bottom 0.254: C10.+ 22.22,43.65 23.47,42.4 IC6.1
N$29
  Bottom 0.254: C10.- 19.55,39.97 21.58,37.94 IC6.3 23.49,37.94
N$30  (via drill 0.5)
  Top 0.254: SV4.12 69.21,41.11 67.3,41.11 65.72,39.52 61.59,39.52 60.16,40.95 60.16,44.76 60.16,45.08 57.94,47.3 v57.62,47.3
  Bottom 0.254: IC2.32 42.04,44.95 41.11,45.87 41.11,54.29 42.7,55.87 50.64,55.87 51.59,54.92 55.24,51.27 57.62,48.89 57.62,47.78 v57.62,47.3
N$31
  Bottom 0.254: C11.+ 26.54,34.89 24.76,36.66 IC6.4
N$32  (via drill 0.5)
  Top 0.254: SV4.13 67.15,38.09 61.11,38.09 58.73,40.48 58.73,43.65 57.62,44.76 v57.62,45.4 | v57.62,45.4
  Bottom 0.254: IC2.31 41.73,44.14 40.64,45.24 40.64,54.45 42.54,56.35 50.8,56.35 58.26,48.89 58.1,49.05 58.41,48.73 58.41,46.19 57.94,45.71 v57.62,45.4
N$33
  Bottom 0.254: IC6.5 24.76,35.39 25.24,34.92 25.24,33.49 26.66,32.06 | 26.66,32.06 | 26.66,32.06 C11.-
N$34  (via drill 0.5)
  Top 0.254: SV4.14 69.21,38.57 61.27,38.57 59.21,40.63 59.21,44.28 v58.57,44.92
  Bottom 0.254: IC2.30 41.58,43.34 40.16,44.76 40.16,54.6 42.38,56.83 50.95,56.83 54.92,52.86 58.89,48.89 58.89,48.41 58.89,45.24 v58.57,44.92
N$35  (via drill 0.5)
  Top 0.254: v49.68,49.68 51.43,49.68 52.22,50.48 54.13,50.48 55.88,48.73 55.88,45.24 57.78,43.33 57.78,43.02 57.78,40.16 60.8,37.14 65.56,37.14 SV4.15 | SV4.15
  Bottom 0.254: IC2.40 49.68,47.7 49.68,48.89 v49.68,49.68 | v49.68,49.68
N$36  (via drill 0.5)
  Top 0.254: v50.64,50.48 51.59,50.48 52.07,50.95 54.29,50.95 56.35,48.89 56.35,45.4 58.26,43.49 58.26,40.32 60.96,37.62 65.88,37.62 67.46,36.03 69.21,36.03 SV4.16 | SV4.16
  Bottom 0.254: IC2.41 50.49,50.33 | 50.49,50.33 50.48,50.32 | 50.49,50.33 v50.64,50.48
N$37  (via drill 0.5)
  Top 0.254: LED2.A 11.65,62.48 v11.74,62.38
  Bottom 0.254: 6.98,62.22 | R3.1 6.98,62.22 | v11.74,62.38 7.14,62.38 6.98,62.22
N$38  (via drill 0.5)
  Top 0.254: v51.27,37.78 50.95,37.46 50.95,35.71 | 50.95,35.71 | 50.95,35.71 50.95,30.95 57.78,24.12 57.78,22.7 58.73,21.74 64.13,21.74 66.35,19.52 SV4.27
  Bottom 0.254: IC2.23 44.57,37.74 45.56,38.73 48.26,38.73 49.24,37.74 51.3,37.74 v51.27,37.78
N$39  (via drill 0.5)
  Top 0.254: v52.38,31.74 60.8,31.74 SV4.23
  Bottom 0.254: IC2.19 47.29,35.09 48.57,33.81 50.64,31.74 v52.38,31.74
N$40  (via drill 0.5)
  Top 0.254: v53.18,30.95 53.49,31.27 60.64,31.27 65.56,26.35 65.56,24.92 67.3,23.17 69.05,23.17 SV4.24
  Bottom 0.254: IC2.20 46.49,35.25 48.73,33.01 | 48.73,33.01 | 48.73,33.01 50.8,30.95 52.38,30.95 v53.18,30.95
N$41  (via drill 0.5)
  Top 0.254: v53.97,30.16 54.61,30.79 54.76,30.79 60.48,30.79 65.08,26.19 65.08,24.12 67.15,22.06 SV4.25
  Bottom 0.254: IC2.21 45.69,35.26 50.8,30.16 v53.97,30.16
N$42  (via drill 0.5)
  Top 0.254: v54.76,29.36 55.72,30.31 60.32,30.31 64.61,26.03 64.61,23.65 67.46,20.79 69.21,20.79 SV4.26
  Bottom 0.254: IC2.22 44.89,35.27 48.41,31.74 | 48.41,31.74 | 48.41,31.74 50.8,29.36 v54.76,29.36
N$43  (via drill 0.5)
  Top 0.254: v51.91,38.73 52.07,38.57 52.07,37.46 51.43,36.82 51.43,35.87 | 51.43,35.87 | 51.43,35.87 51.43,31.11 58.26,24.28 58.26,23.01 59.05,22.22 60,22.22 64.29,22.22 65.4,21.11 v65.88,21.11
  Bottom 0.254: IC2.24 44.74,38.55 45.4,39.2 48.41,39.2 49.07,38.55 51.72,38.55 v51.91,38.73 | v65.88,21.11 66.19,20.79 69.21,20.79 SV4.28
N$44  (via drill 0.5)
  Top 0.254: v50.32,39.36 50,39.05 50,30.63 56.83,23.81 56.83,22.22 58.26,20.79 63.81,20.79 67.62,16.98 SV4.29 | v50.32,39.36
  Bottom 0.254: IC2.25 44.74,39.34 45.08,39.68 50,39.68 v50.32,39.36
N$45  (via drill 0.5)
  Top 0.254: v51.11,40.16 51.11,38.73 50.48,38.09 50.48,35.39 50.48,30.79 57.3,23.96 57.3,22.54 58.57,21.27 63.97,21.27 66.99,18.25 69.21,18.25 SV4.30
  Bottom 0.254: IC2.26 51.1,40.14 v51.11,40.16
N$46
  Bottom 0.254: IC2.15 50.49,36.02 50.48,36.03 50.48,35.08 52.07,33.49 52.54,33.49 56.67,29.36 56.67,22.54 67.3,11.9 SV4.33
N$47  (via drill 0.5)
  Top 0.254: v51.91,40.95 51.43,41.43 v51.43,43.97 | v43.65,52.54 44.29,52.54 50.48,58.73 v50.48,60.8
  Bottom 0.254: SV4.32 69.21,13.17 66.67,13.17 57.15,22.7 57.15,29.52 52.7,33.97 52.38,33.97 51.29,35.06 IC2.14 51.29,36.68 51.75,37.14 52.38,37.14 52.7,37.46 52.7,40.16 v51.91,40.95 | v51.43,43.97 51.43,44.28 52.22,45.08 54.45,47.3 54.45,48.89 49.84,53.49 45.87,53.49 44.92,52.54 v43.65,52.54 | 52.13,60.86 52.22,60.95 | 52.13,60.86 SJ1.3 | v50.48,60.8 51.91,60.8 52.13,60.86
N$48
  Bottom 0.254: IC2.13 52.09,35.05 52.7,34.44 52.86,34.44 57.62,29.68 57.62,22.85 66.03,14.44 SV4.31
OE  (via drill 0.5)
  Top 0.254: X2.9 45.4,26.98 v45.56,27.14 | v45.56,27.14 | v48.26,27.14 49.05,27.93 49.05,43.65 43.33,49.37 38.73,49.37 37.79,48.42 IC1.37
  Bottom 0.254: v45.56,27.14 v48.26,27.14
REG  (via drill 0.5)
  Top 0.254: X2.44 32.06,28.41 v33.33,29.68 | v47.78,30.47 48.1,30.79 48.1,43.33 43.02,48.41 | IC1.34 40.3,47.45 40.16,47.14 | 43.02,48.41 | 43.02,48.41 40.32,48.41 40.16,48.25 40.16,47.14 | 40.16,47.14
  Bottom 0.254: v33.33,29.68 33.65,29.36 46.67,29.36 v47.78,30.47
RESET  (via drill 0.5)
  Top 0.254: 53.97,14.44 44.6,14.44 42.54,12.38 42.22,12.38 42.17,12.32 R4.1 40.53,12.32 38.89,13.96 38.89,15.39 38.93,15.43 S1.2 | 53.97,14.44 SV1.5 | 52.7,43.97 54.45,42.22 54.45,39.05 59.69,33.81 | v63.18,33.33 62.7,33.81 59.69,33.81 | 59.69,33.81 | v63.5,18.09 62.38,16.98 57.62,16.98 55.88,16.98 55.24,16.34 55.24,14.92 54.76,14.44 54.61,14.44 53.97,14.44 | SV1.5 53.97,13.01 | SV1.5 53.97,14.44 | 52.7,43.97 v52.54,43.65 52.7,43.97 | 52.7,43.97 50.95,45.71 48.26,45.71 43.65,50.32 39.52,50.32 v39.21,50.63
  Bottom 0.254: IC3.10 IC3.11 | IC3.10 33.28,55.18 33.33,55.24 | IC3.10 34.39,55.18 34.44,55.24 | IC2.4 52.85,43.34 v52.54,43.65 | v63.18,33.33 64.13,32.38 64.13,18.88 63.97,18.73 | v63.5,18.09 63.65,18.25 63.65,18.41 63.97,18.73 | 63.97,18.73 | v39.21,50.63 39.21,51.43 35.55,55.08 34.6,55.08 34.44,55.24 | 34.44,55.24 IC3.9 | S1.2 38.93,15.43 38.89,15.39 38.85,15.43 S1.1
RST  (via drill 0.5)
  Top 0.254: IC1.14 33.79,35.06 30.63,31.9 v30.63,31.27 | X2.41 35.87,27.93 37.46,29.52 v37.46,30.47 | v30.63,31.27
  Bottom 0.254: v37.46,30.47 31.9,30.47 31.43,30.47 v30.63,31.27
RXD  (via drill 0.5)
  Top 0.254: v71.43,54.76 71.75,54.45 71.75,48.73 SV4.6
  Bottom 0.254: IC2.9 57.76,39.34 62.7,44.28 63.81,44.28 66.67,47.14 66.67,47.94 67.46,48.73 68.57,48.73 69.84,47.46 SV4.6 | SJ2.1 50.45,59.05 60.8,59.05 64.13,55.71 70.48,55.71 v71.43,54.76 | v71.43,54.76
RXD_MAX  (via drill 0.5)
  Top 0.254: v38.41,60.64 36.83,62.22 21.9,62.22 11.27,51.59 11.27,35.71 v11.58,35.39 | v11.58,35.39
  Bottom 0.254: v38.41,60.64 47.14,60.64 47.33,60.76 SJ2.2 48.73,60.8 | v11.58,35.39 IC6.12
SCK  (via drill 0.5)
  Top 0.254: v20.63,18.88 20.63,20.15 23.17,22.7 23.17,59.52 24.28,60.64 29.52,60.64 v30.63,59.52
  Bottom 0.254: SV1.7 56.51,12.54 53.97,10 44.45,10 40.79,13.65 30.95,13.65 30.16,14.44 30.16,16.34 28.41,18.09 21.43,18.09 v20.63,18.88 | v30.63,59.52 IC3.5
SCK_I  (via drill 0.5)
  Top 0.254: SV4.22 69.05,25.71 67.78,25.71 67.46,25.71 64.13,29.04 64.13,33.81 63.65,34.28 59.84,34.28 54.92,39.2 54.92,42.38 51.11,46.19 48.41,46.19 43.81,50.79 40.16,50.79 39.52,51.43 38.89,51.43 v37.14,49.68 | IC1.43 33.01,47.46 33.02,47.46 v33.02,48.89 | v24.92,51.27 v28.25,51.27
  Bottom 0.254: v37.14,49.68 36.51,48.89 v33.02,48.89 30.63,48.89 v28.25,51.27 | v24.92,51.27 24.6,51.59 24.6,56.67 25.24,57.3 26.19,57.3 28.09,59.21 IC3.3
SDI  (via drill 0.5)
  Top 0.254: SV4.20 69.21,28.41 67.46,28.41 65.08,30.79 65.08,34.44 64.29,35.24 60.16,35.24 55.88,39.52 55.88,39.68 55.88,42.7 51.43,47.14 48.73,47.14 44.13,51.75 40.48,51.75 39.84,52.38 37.62,52.38 v36.35,51.11 | IC1.39 36.21,47.45 36.19,47.14 IC1.39 | v36.35,51.11 36.19,50.95 IC1.39 | v36.35,51.11
  Bottom 0.254: v36.35,51.11 30.95,51.11 29.52,52.54 IC3.13 29.36,55.24
SDO  (via drill 0.5)
  Top 0.254: SV4.21 66.35,28.73 64.61,30.47 64.61,31.9 64.61,34.12 63.97,34.76 60,34.76 55.4,39.36 55.4,42.54 51.27,46.67 48.57,46.67 43.97,51.27 40.32,51.27 39.68,51.91 38.25,51.91 v37.46,51.11 | SV4.21 | IC1.40 35.4,47.3 | IC1.40 | IC1.40 v35.4,53.02 | v35.4,53.02 | v35.4,53.02 32.7,55.71 28.89,55.71 v25.55,59.05
  Bottom 0.254: 37.46,52.38 36.83,53.02 v35.4,53.02 | 37.46,52.38 | 37.46,52.38 v37.46,51.11 | v25.55,59.05 IC3.1
SPI2CF_ENABLE  (via drill 0.5)
  Top 0.254: SV4.18 69.21,33.49 66.99,33.49 66.67,33.81 66.67,35.24 65.24,36.66 60.64,36.66 57.3,40 57.3,43.17 55.4,45.08 55.4,48.57 54.29,49.68 v52.54,49.68 | v42.38,52.54 42.06,52.22 40.64,52.22 40,52.86 36.83,52.86 v36.19,52.22 | IC1.41 34.6,47.46 v34.6,52.22
  Bottom 0.254: v52.54,49.68 | v52.54,49.68 52.54,49.05 | 52.54,49.05 52.54,49.21 | 52.54,49.05 52.07,48.57 52.07,48.41 52.07,47.94 52.09,47.59 IC2.43 | v52.54,49.68 52.54,50.16 49.68,53.02 46.03,53.02 44.76,51.75 43.18,51.75 v42.38,52.54 | v34.6,52.22 v36.19,52.22
SS  (via drill 0.5)
  Top 0.254: SV4.19 | SV4.19 65.56,32.06 65.56,34.76 64.61,35.71 60.32,35.71 56.35,39.68 56.35,42.86 53.65,45.55 v53.65,47.62 | IC1.33 45.05,45.74 47.3,43.49 v47.3,42.7
  Bottom 0.254: 52.86,47.62 v53.65,47.62 | 52.86,47.62 52.89,47.59 IC2.44 | 52.86,47.62 52.86,46.51 52.38,46.03 49.53,46.03 47.3,43.81 v47.3,42.7
TXD  (via drill 0.5)
  Top 0.254: SV4.5 69.21,48.73 69.21,55.87 v69.84,56.51
  Bottom 0.254: IC2.10 57.6,38.55 62.86,43.81 63.97,43.81 67.62,47.46 SV4.5 | SJ1.1 54.92,61.05 55.08,60.8 55.08,59.84 55.4,59.52 60.96,59.52 64.29,56.19 69.53,56.19 v69.84,56.51
TXD_MAX  (via drill 0.5)
  Top 0.254: v40.32,62.7 21.58,62.7 10.79,51.75 10.79,48.89 10.79,49.05 10.79,34.6 v11.27,34.12
  Bottom 0.254: v40.32,62.7 52.86,62.7 53.65,61.91 SJ1.2 55.24,60.8 | v11.27,34.12 IC6.11
V33  (via drill 0.5)
  Top 0.254: X2.38 X2.13 | X2.38 39.64,21.79 39.68,21.84 39.68,28.57 44.76,33.65 v44.76,34.12 | X2.32 47.3,19.2 46.51,18.41 40.16,18.41 39.68,18.88 v39.68,19.36 X2.38 | v38.1,39.2 | v38.1,39.2 38.1,40.16 42.38,40.16 42.37,40.14 IC1.26 | IC1.35 39.39,44.79 38.1,43.49 v38.1,39.2 | IC1.15 34.59,38.4 v35.4,39.2
  Top 0.61: v45.56,12.06 | v45.56,12.06 45.56,11.42 SV3.4 | v15.08,20 15.08,21.58 v10.63,26.03
  Bottom 0.254: 4.92,44.76 4.86,44.82 C2.1 4.92,44.92 5.08,44.76 | v44.76,34.12 44.6,34.28 42.38,36.51 39.05,36.51 38.1,37.46 v38.1,39.2 v35.4,39.2 | v15.08,20 | v15.08,20 15.08,20.15 v15.08,20 | 2.85,48.73 C1.+
  Bottom 0.406: 69.21,51.27 SV4.3 68.42,50 69.69,48.73 72.38,48.73 | 69.21,51.27 72.07,51.27 72.38,50.95 | 69.21,51.27 69.21,53.17 68.1,54.29 61.91,54.29 59.84,52.38 C7.1 59.53,52.38
  Bottom 0.61: v15.08,20 39.05,20 v39.68,19.36 | v39.68,19.36 | v45.56,12.06 45.56,15.71 42.86,18.41 40.16,18.41 39.68,18.88 v39.68,19.36 | SV3.4 53.49,7.61 62.07,7.61 63.5,6.18 69.05,6.18 72.38,9.52 72.38,48.73 72.38,50.95
  Bottom 0.813: 5.08,44.76 4.28,44.76 2.85,46.19 2.85,48.73 | v10.63,26.03 9.52,27.14 | 9.52,27.14 | 9.52,27.14 9.52,35.71 8.09,37.14 IC4.3 | IC4.3 | IC4.3 8.09,40.48 4.92,43.65 4.92,45.08 4.86,45.02 C2.1
V+
  Bottom 0.254: 26.66,37.62 | 26.66,37.62 C8.+ | IC6.2 25.08,39.2 26.66,37.62
V-
  Bottom 0.254: C9.- 13.52,42.99 14.44,42.06 18.57,42.06 19.04,41.59 19.04,39.84 21.58,37.3 21.58,34.76 22.22,34.12 IC6.6 23.65,34.12
VCC  (via drill 0.5, 0.6)
  Top 0.254: v50.32,40.95 50.32,41.11 | v46.67,40.95 46.35,41.27 46.35,42.22 46.19,42.38 45.4,43.17 v45.4,43.65 | v45.4,43.65 | v46.67,40.95 | v46.67,40.95 v46.67,37.94
  Top 0.61: 50.32,41.11 v50.32,43.02 | R4.2 43.07,14.02 44.76,15.71 SV1.2 | v9.52,41.59 3.8,41.59 3.01,40.79 IC4.1 | IC4.1 | IC5.3 | IC5.3 11.11,20.79 v13.01,20.79 | v41.59,10.15 42.06,10.15 45.24,13.33 v46.83,13.33
  Bottom 0.254: 67.94,52.38 SV4.1 | SV4.1 | SV4.1 | 31.07,44.09 C4.+ 30.79,44.92 | IC2.5 | IC2.27 | IC2.38 48.1,46.35 v45.39,43.64 v45.4,43.65 | IC2.17 48.89,37.3 48.26,37.94 v46.67,37.94 | 33.02,40.95 32.7,40.95 32.7,41.27 C6.1 32.59,41.37 32.54,41.43 32.54,40.48 | 26.66,40.48 C8.- 26.66,40.48 | 26.66,40.95 26.66,40.48 | v46.67,40.95 | 33.02,44.92
  Bottom 0.61: IC2.5 58.1,42.55 67.94,52.38 | v50.32,43.02 51.59,43.02 51.75,43.02 52.22,42.54 IC2.5 | v50.32,40.95 v46.67,40.95 IC2.27 34.29,40.95 | 30.79,44.92 30.16,45.24 30.16,47.62 29.36,48.41 25.55,52.22 IC3.16 | 33.02,40.95 34.29,40.95 | 34.29,44.92 33.02,44.92 C4.+ | R1.1 34.44,45.08 34.29,44.92 | 34.29,40.95 34.29,44.92 | 26.66,40.95 23.97,43.65 23.97,44.76 23.01,45.71 11.9,45.71 9.52,43.33 v9.52,41.59 10.47,40.48 IC6.16 | 26.66,40.48 29.05,40.48 29.52,40 32.06,40 32.54,40.48 | v13.01,20.79 13.01,19.52 15.87,16.82 27.93,16.82 28.89,15.87 28.89,13.49 30,12.38 40.48,12.38 41.59,11.27 v41.59,10.15 | v46.83,13.33 46.83,14.92 47.62,15.71 SV1.2
  Bottom 0.813: IC5.3 8.25,20.79 1.9,27.14 1.9,37.94 3.17,39.2 IC4.1
WE  (via drill 0.5)
  Top 0.254: X2.36 42.22,29.84 44.92,32.54 v45.4,32.54 | v49.84,29.2 49.53,29.52 49.53,35.08 49.53,43.81 43.49,49.84 38.57,49.84 36.99,48.26 | 36.99,48.26 IC1.38 | 36.99,48.26 36.98,48.25
  Bottom 0.254: v45.4,32.54 46.83,32.54 49.84,29.68 v49.84,29.2

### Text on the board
tNames: SPI2CF - (c) 2006 | Till Harbaum | V1.1 | + | -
